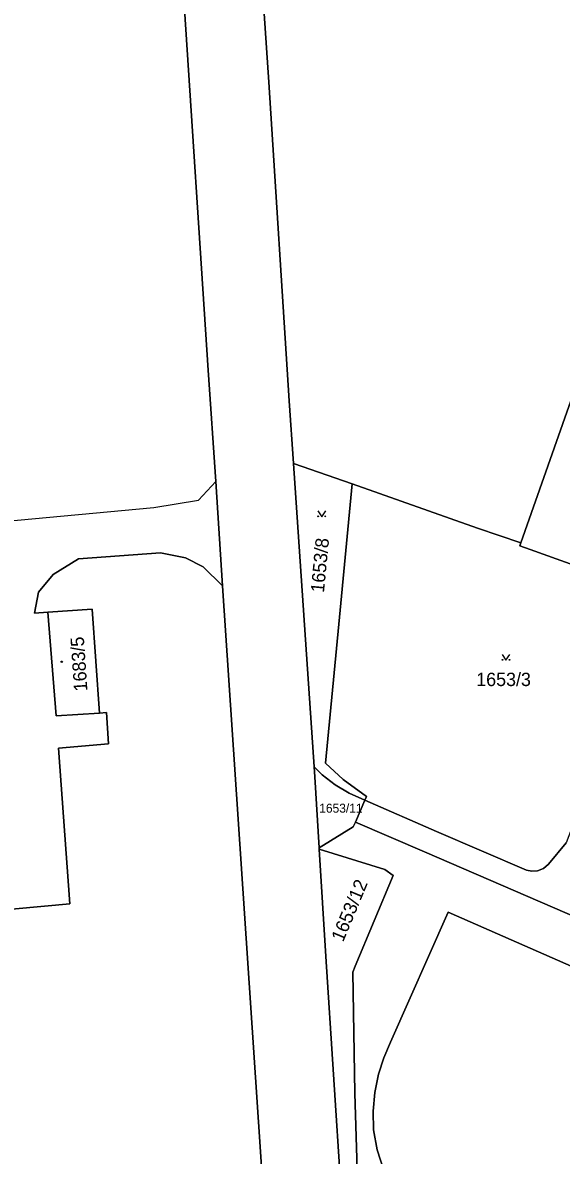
# Model space of a CAD drawing. Extents: x -596024 to -594475, y -1163820 to -1161957.
# Drawn here: x -595891.6 to -595823.2, y -1162318.6 to -1162174.7 of the extents above; entities that cross this region are included whole.
import ezdxf

# ---------------------------------------------------------------- set-up
doc = ezdxf.new("R2010")
doc.units = 0
for name, color, linetype in [('Level 1', 7, 'Continuous'), ('Level 4', 7, 'Continuous'), ('Level 5', 7, 'Continuous'), ('Level 60', 7, 'Continuous'), ('Vrstva 60', 7, 'Continuous')]:
    doc.layers.add(name, color=color, linetype=linetype)

msp = doc.modelspace()

# ---------------------------------------------------------------- linework, layer by layer
at = {"layer": 'Level 1'}
for points in [[(-595857.22, -1162230.69), (-595857.76, -1162222.73), (-595860.33, -1162182.22), (-595864.54, -1162120.48), (-595865.08, -1162105.24), (-595865.01, -1162103.26), (-595864.9, -1162102.99)], [(-595874.09, -1162128.33), (-595871.23, -1162170.34), (-595868.05, -1162218.83), (-595867.1, -1162233)], [(-595798.39, -1162211.43), (-595815.82, -1162205.27), (-595828.32, -1162240.78)], [(-595857.22, -1162230.69), (-595849.74, -1162233.3)], [(-595854.6, -1162269.24), (-595857.22, -1162230.69)], [(-595937.78, -1162261.82), (-595942.61, -1162262.22), (-595944.82, -1162239.26), (-595938.77, -1162238.8), (-595938.38, -1162243.31), (-595937.25, -1162244.43), (-595911.31, -1162242.35), (-595911.49, -1162239.66), (-595874.94, -1162236.3), (-595869.29, -1162235.36), (-595867.1, -1162233)], [(-595867.1, -1162233), (-595866.22, -1162246.24)], [(-595848.14, -1162273.48), (-595847.95, -1162273.04), (-595850.89, -1162270.88), (-595853.15, -1162268.79), (-595851.44, -1162251.11), (-595849.74, -1162233.3)], [(-595849.74, -1162233.3), (-595833.81, -1162238.93), (-595828.32, -1162240.78)], [(-595810.87, -1162247.24), (-595810.93, -1162247.42), (-595827.12, -1162241.64), (-595828.45, -1162241.16), (-595828.32, -1162240.78)], [(-595888.42, -1162249.6), (-595890.12, -1162249.71), (-595889.62, -1162247.05), (-595887.74, -1162244.82), (-595884.55, -1162242.82), (-595874.12, -1162242.07), (-595870.93, -1162242.7), (-595868.67, -1162243.83), (-595866.22, -1162246.24)], [(-595866.22, -1162246.24), (-595859.47, -1162347.22), (-595855.6, -1162406.13), (-595852.65, -1162447.92), (-595854.56, -1162448.05)], [(-595810.87, -1162247.24), (-595810.54, -1162247.36), (-595822.56, -1162278.91), (-595824.79, -1162281.63), (-595825.42, -1162282.16), (-595826.18, -1162282.47), (-595826.9, -1162282.53), (-595827.6, -1162282.39), (-595839.05, -1162277.47), (-595848.14, -1162273.48)], [(-595881.87, -1162262.42), (-595882.78, -1162249.23), (-595888.42, -1162249.6)], [(-595888.42, -1162249.6), (-595887.38, -1162262.79), (-595881.87, -1162262.42)], [(-595907.37, -1162281.61), (-595906.86, -1162288.6), (-595885.63, -1162286.66), (-595887.06, -1162266.87), (-595880.72, -1162266.33), (-595880.99, -1162262.36), (-595881.87, -1162262.42)], [(-595848.14, -1162273.48), (-595850.14, -1162272.59), (-595851.92, -1162271.53), (-595853.55, -1162270.27), (-595854.6, -1162269.24)], [(-595854.6, -1162269.24), (-595854.51, -1162270.53), (-595853.95, -1162279.53)], [(-595848.14, -1162273.48), (-595849.35, -1162276.28)], [(-595853.95, -1162279.53), (-595849.62, -1162276.89), (-595849.35, -1162276.28)], [(-595804.6, -1162295.61), (-595840.55, -1162280.07), (-595849.35, -1162276.28)], [(-595853.94, -1162279.72), (-595853.95, -1162279.53)], [(-595853.94, -1162279.72), (-595845.61, -1162282.29), (-595844.56, -1162283.08), (-595849.38, -1162294.6), (-595849.67, -1162295.34), (-595849.42, -1162310.72), (-595848.46, -1162342.58), (-595847.77, -1162368.33)], [(-595853.94, -1162279.72), (-595853.09, -1162293.36), (-595848.22, -1162368.36)], [(-595845.79, -1162320.43), (-595846.57, -1162317.95), (-595847.03, -1162315.39), (-595847.09, -1162313.01), (-595846.88, -1162310.63), (-595846.4, -1162308.3), (-595845.74, -1162306.24), (-595844.87, -1162304.26), (-595837.57, -1162287.72), (-595806.99, -1162301.14), (-595804.6, -1162295.61)]]:
    msp.add_lwpolyline(points, dxfattribs=at)
at = {"layer": 'Level 5'}
for points in [[(-595854.12, -1162236.72), (-595853.62, -1162237.47), (-595853.12, -1162236.72)], [(-595830.71, -1162254.96), (-595830.21, -1162255.71), (-595829.71, -1162254.96)]]:
    msp.add_lwpolyline(points, dxfattribs=at)
for centre, radius in [((-595854.07, -1162237.42), 0.05), ((-595853.17, -1162237.42), 0.05), ((-595886.66, -1162255.9), 0.09), ((-595886.66, -1162255.9), 0.0521), ((-595830.66, -1162255.66), 0.05), ((-595829.76, -1162255.66), 0.05)]:
    msp.add_circle(centre, radius, dxfattribs=at)
at = {"layer": 'Level 60'}
for points in [[(-595714.28, -1162100.65), (-595763.48, -1162212.38), (-595762.1, -1162212.98), (-595764.81, -1162215.77), (-595768.57, -1162216.89), (-595770.91, -1162217.26), (-595776.23, -1162216.55), (-595795.42, -1162208.87), (-595797.46, -1162209.91), (-595798.39, -1162211.43), (-595815.82, -1162205.27), (-595828.32, -1162240.78), (-595833.81, -1162238.93), (-595849.74, -1162233.3), (-595857.22, -1162230.69), (-595857.76, -1162222.73), (-595860.33, -1162182.22), (-595864.54, -1162120.48)], [(-595864.54, -1162120.48), (-595860.33, -1162182.22), (-595857.76, -1162222.73), (-595857.22, -1162230.69), (-595854.6, -1162269.24), (-595854.51, -1162270.53), (-595853.95, -1162279.53), (-595853.94, -1162279.72), (-595853.09, -1162293.36), (-595848.22, -1162368.36), (-595847.7, -1162376.42), (-595847.64, -1162393.56)], [(-595855.6, -1162406.13), (-595859.47, -1162347.22), (-595866.22, -1162246.24), (-595867.1, -1162233), (-595868.05, -1162218.83), (-595871.23, -1162170.34)], [(-595810.93, -1162247.42), (-595827.12, -1162241.64), (-595828.45, -1162241.16), (-595828.32, -1162240.78), (-595815.82, -1162205.27)], [(-595911.49, -1162239.66), (-595874.94, -1162236.3), (-595869.29, -1162235.36), (-595867.1, -1162233), (-595866.22, -1162246.24), (-595868.67, -1162243.83), (-595870.93, -1162242.7), (-595874.12, -1162242.07), (-595884.55, -1162242.82), (-595887.74, -1162244.82), (-595889.62, -1162247.05), (-595890.12, -1162249.71), (-595888.42, -1162249.6), (-595887.38, -1162262.79), (-595881.87, -1162262.42), (-595880.99, -1162262.36), (-595880.72, -1162266.33), (-595887.06, -1162266.87), (-595885.63, -1162286.66), (-595906.86, -1162288.6)], [(-595804.6, -1162295.61), (-595840.55, -1162280.07), (-595849.35, -1162276.28), (-595848.14, -1162273.48), (-595839.05, -1162277.47), (-595827.6, -1162282.39), (-595826.9, -1162282.53), (-595826.18, -1162282.47), (-595825.42, -1162282.16), (-595824.79, -1162281.63), (-595822.56, -1162278.91)], [(-595848.46, -1162342.58), (-595849.42, -1162310.72), (-595849.67, -1162295.34), (-595849.38, -1162294.6), (-595844.56, -1162283.08), (-595845.61, -1162282.29), (-595853.94, -1162279.72), (-595853.95, -1162279.53), (-595849.62, -1162276.89), (-595849.35, -1162276.28), (-595840.55, -1162280.07), (-595804.6, -1162295.61), (-595806.99, -1162301.14), (-595837.57, -1162287.72), (-595844.87, -1162304.26), (-595845.74, -1162306.24), (-595846.4, -1162308.3), (-595846.88, -1162310.63), (-595847.09, -1162313.01), (-595847.03, -1162315.39), (-595846.57, -1162317.95), (-595845.79, -1162320.43)], [(-595845.79, -1162320.43), (-595846.57, -1162317.95), (-595847.03, -1162315.39), (-595847.09, -1162313.01), (-595846.88, -1162310.63), (-595846.4, -1162308.3), (-595845.74, -1162306.24), (-595844.87, -1162304.26), (-595837.57, -1162287.72), (-595806.99, -1162301.14), (-595804.6, -1162295.61), (-595780.44, -1162306.15), (-595765.76, -1162312.62), (-595756.34, -1162316.64), (-595756.42, -1162316.82), (-595766.21, -1162339.62)]]:
    msp.add_lwpolyline(points, dxfattribs=at)
for points in [[(-595847.95, -1162273.04), (-595848.14, -1162273.48), (-595850.14, -1162272.59), (-595851.92, -1162271.53), (-595853.55, -1162270.27), (-595854.6, -1162269.24), (-595857.22, -1162230.69), (-595849.74, -1162233.3), (-595851.44, -1162251.11), (-595853.15, -1162268.79), (-595850.89, -1162270.88)], [(-595827.12, -1162241.64), (-595810.93, -1162247.42), (-595810.87, -1162247.24), (-595810.54, -1162247.36), (-595822.56, -1162278.91), (-595824.79, -1162281.63), (-595825.42, -1162282.16), (-595826.18, -1162282.47), (-595826.9, -1162282.53), (-595827.6, -1162282.39), (-595839.05, -1162277.47), (-595848.14, -1162273.48), (-595847.95, -1162273.04), (-595850.89, -1162270.88), (-595853.15, -1162268.79), (-595851.44, -1162251.11), (-595849.74, -1162233.3), (-595833.81, -1162238.93), (-595828.32, -1162240.78), (-595828.45, -1162241.16)], [(-595887.38, -1162262.79), (-595888.42, -1162249.6), (-595882.78, -1162249.23), (-595881.87, -1162262.42)], [(-595850.14, -1162272.59), (-595848.14, -1162273.48), (-595849.35, -1162276.28), (-595849.62, -1162276.89), (-595853.95, -1162279.53), (-595854.51, -1162270.53), (-595854.6, -1162269.24), (-595853.55, -1162270.27), (-595851.92, -1162271.53)], [(-595853.94, -1162279.72), (-595845.61, -1162282.29), (-595844.56, -1162283.08), (-595849.38, -1162294.6), (-595849.67, -1162295.34), (-595849.42, -1162310.72), (-595848.46, -1162342.58), (-595847.77, -1162368.33), (-595848.22, -1162368.36), (-595853.09, -1162293.36)]]:
    msp.add_lwpolyline(points, close=True, dxfattribs=at)
at = {"layer": 'Vrstva 60'}
for points in [[(-595911.49, -1162239.66), (-595874.94, -1162236.3), (-595869.29, -1162235.36), (-595867.1, -1162233), (-595868.05, -1162218.83), (-595871.23, -1162170.34)], [(-595855.6, -1162406.13), (-595859.47, -1162347.22), (-595866.22, -1162246.24), (-595868.67, -1162243.83), (-595870.93, -1162242.7), (-595874.12, -1162242.07), (-595884.55, -1162242.82), (-595887.74, -1162244.82), (-595889.62, -1162247.05), (-595890.12, -1162249.71), (-595888.42, -1162249.6), (-595882.78, -1162249.23), (-595881.87, -1162262.42), (-595880.99, -1162262.36), (-595880.72, -1162266.33), (-595887.06, -1162266.87), (-595885.63, -1162286.66), (-595906.86, -1162288.6)]]:
    msp.add_lwpolyline(points, dxfattribs=at)

# ---------------------------------------------------------------- texts
at = {"layer": 'Level 4'}
for s, rotation, p in [('1653/8', 84.5475, (-595853.34, -1162247.17)), ('1683/5', 93.9467, (-595883.39, -1162259.6)), ('1653/12', 67.2954, (-595850.91, -1162291.61))]:
    msp.add_text(s, height=1.7, rotation=rotation, dxfattribs=at).set_placement(p)
for s, height, p in [('1653/3', 1.7, (-595833.99, -1162258.99)), ('1653/11', 1.14, (-595853.94, -1162275.08))]:
    msp.add_text(s, height=height, dxfattribs=at).set_placement(p)

doc.saveas('drawing.dxf')
